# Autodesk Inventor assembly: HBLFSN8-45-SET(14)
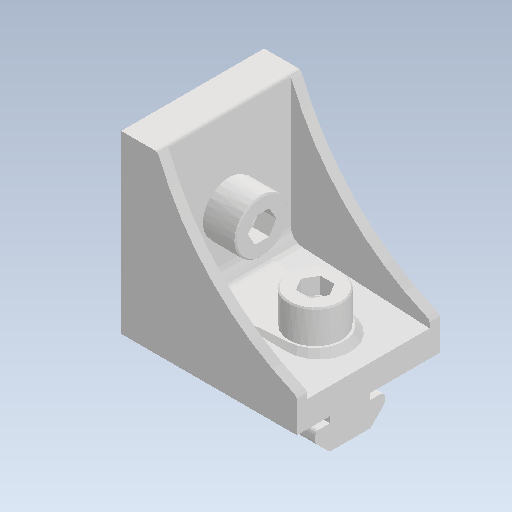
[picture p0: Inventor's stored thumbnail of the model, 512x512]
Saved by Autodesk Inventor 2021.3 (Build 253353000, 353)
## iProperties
Created: 2022-02
Part Number: HBLFSN8-45-SET(14)
Document SubType Name: Assembly
Designer: kengo
Author: kengo
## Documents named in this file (4)
- C:\Users\kengo\Documents\S2S_frame\SDC345\frame_misumi_ver12\HBLFSN8-45-SET(14).iam
- C:\Users\kengo\Documents\S2S_frame\SDC345\frame_misumi_ver12\HBLFSN8-45.ipt
- C:\Users\kengo\Documents\S2S_frame\SDC345\frame_misumi_ver12\HNTT8-8.ipt
- C:\Users\kengo\Documents\S2S_frame\SDC345\frame_misumi_ver12\CBM8-20.ipt
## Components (5 placed, 3 different names)
1. HBLFSN8-45
2. HNTT8-8
3. CBM8-20
4. HNTT8-8:1
5. CBM8-20:1
